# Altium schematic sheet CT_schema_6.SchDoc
size 368 x 336 mm
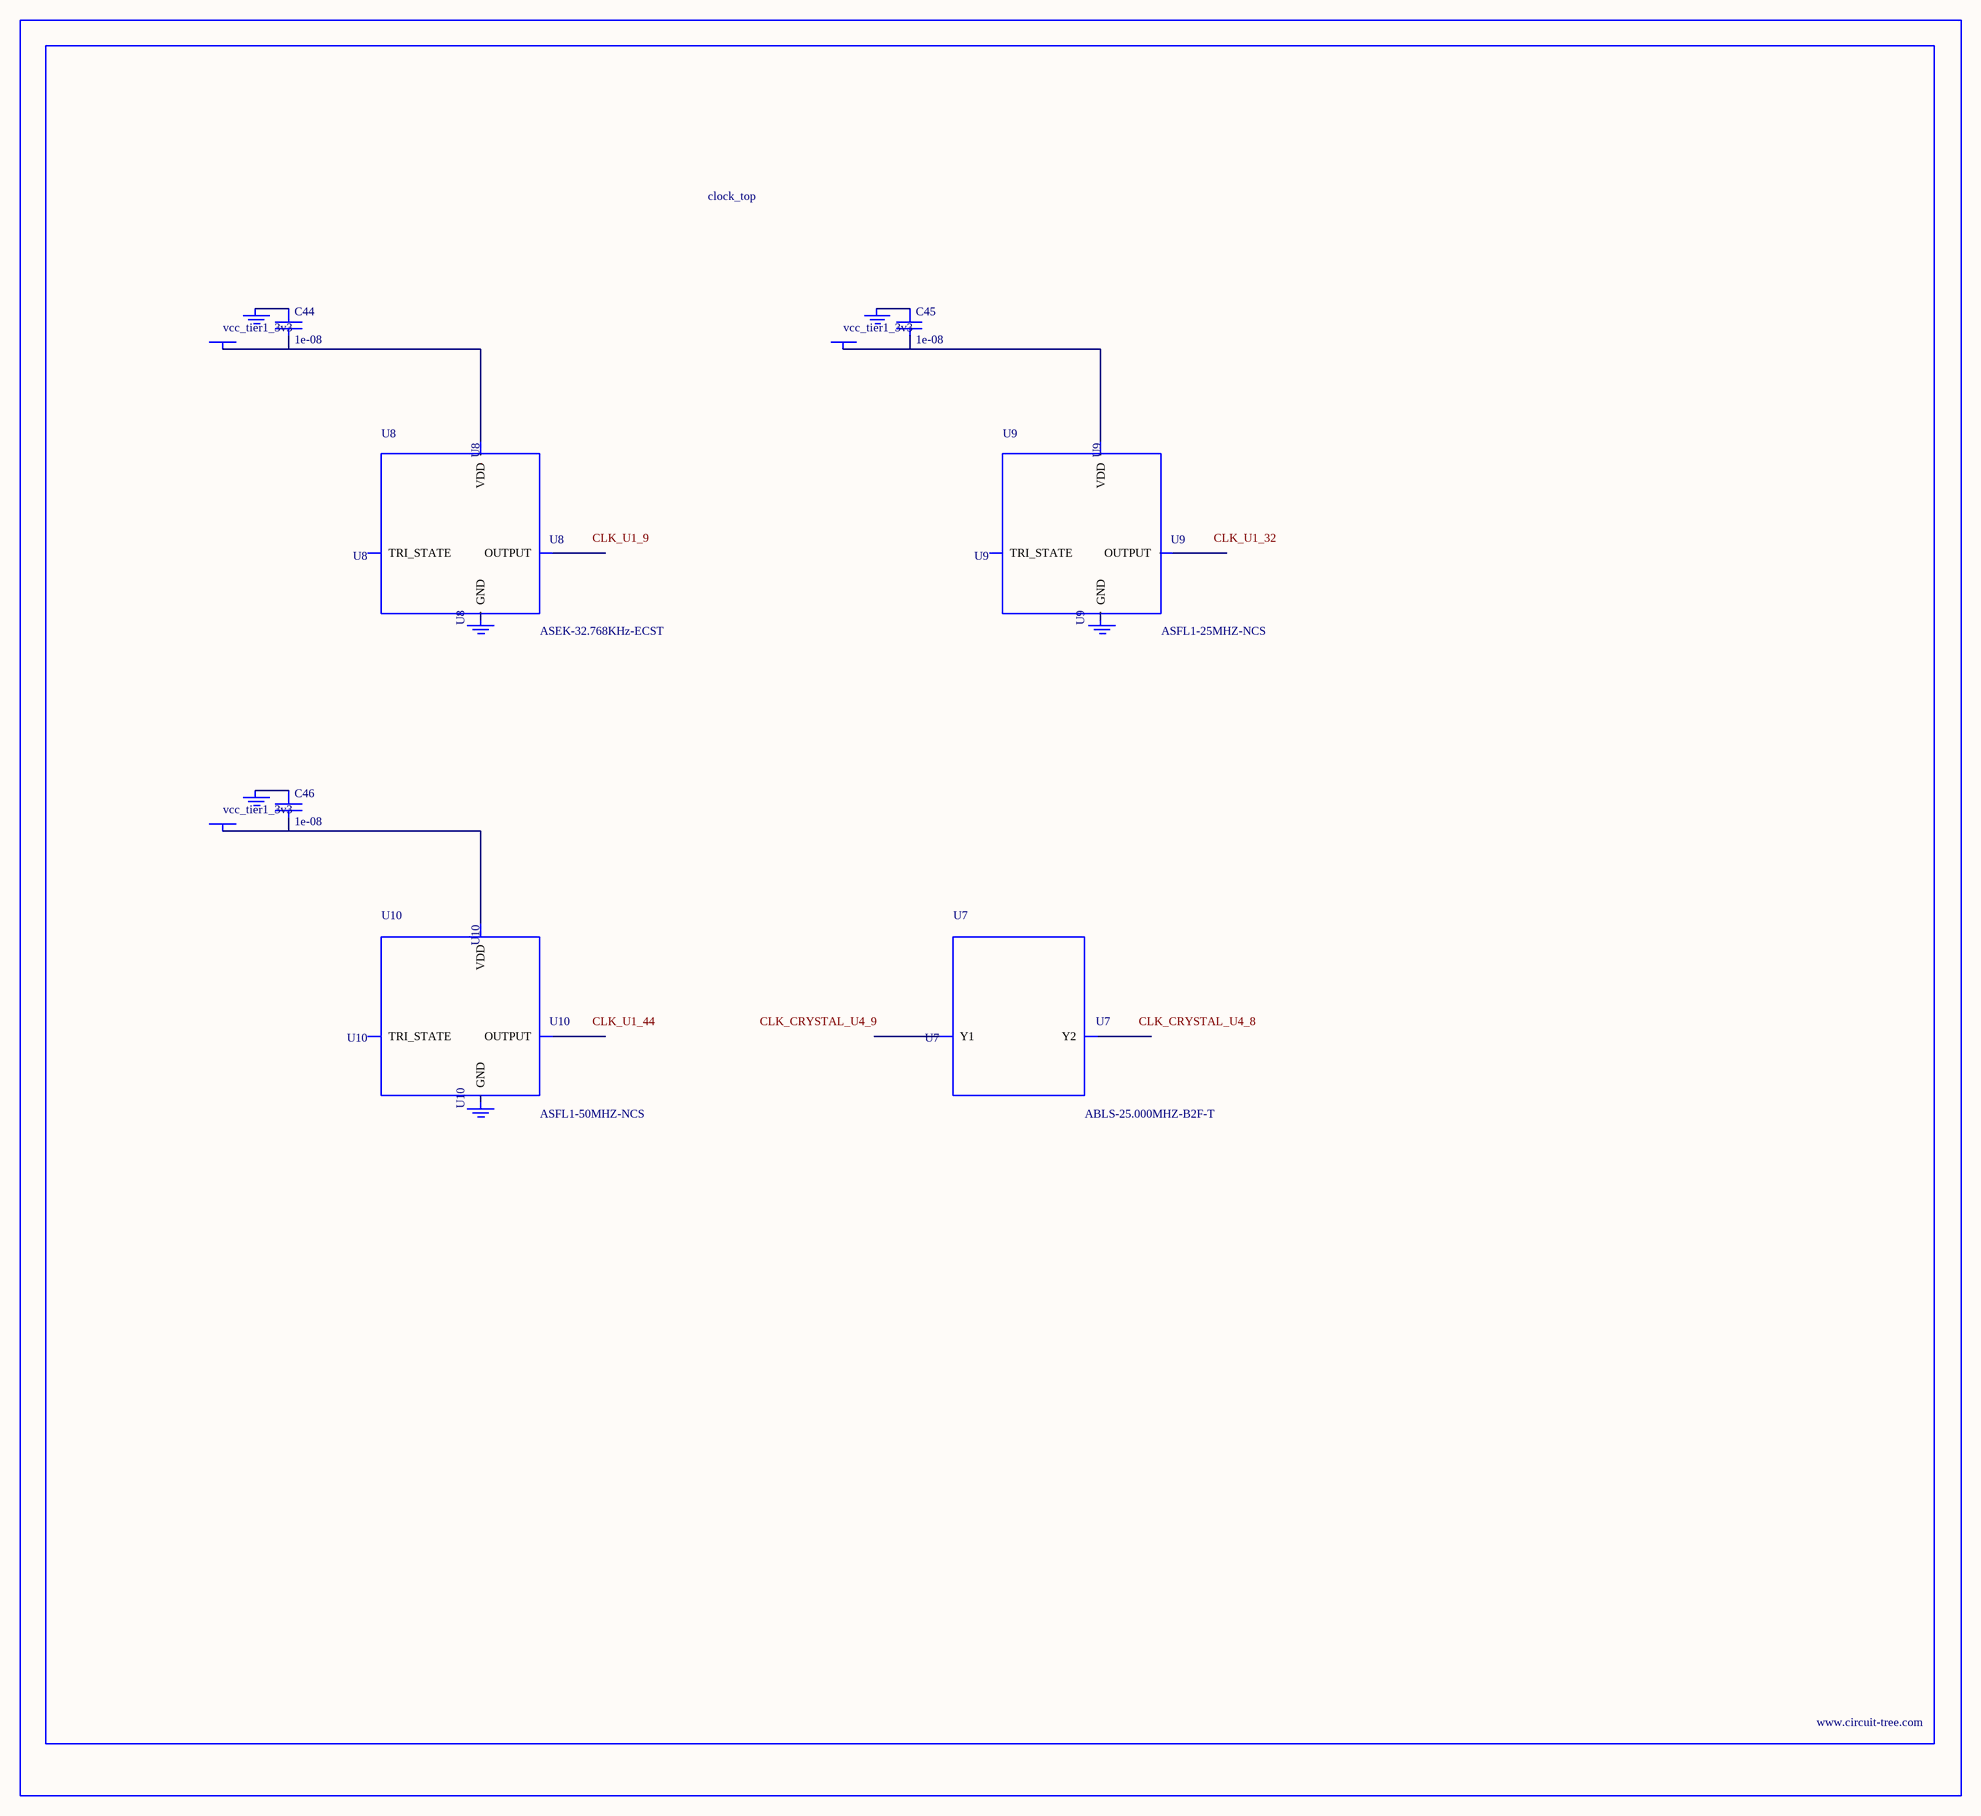
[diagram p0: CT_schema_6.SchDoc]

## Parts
BORDER5  (no value)
C44  1e-08  [C0402]
C45  1e-08  [C0402]
C46  1e-08  [C0402]
GND_INSTANCE_5_0  (no value)
GND_INSTANCE_5_1  (no value)
GND_INSTANCE_5_2  (no value)
GND_INSTANCE_5_3  (no value)
GND_INSTANCE_5_4  (no value)
GND_INSTANCE_5_5  (no value)
POWER_INSTANCE_5_0  vcc_tier1_3v3
POWER_INSTANCE_5_1  vcc_tier1_3v3
POWER_INSTANCE_5_2  vcc_tier1_3v3
U7  ABLS-25.000MHZ-B2F-T  [ABLS-25.000MHZ-B2F-T]
U8  ASEK-32.768KHz-ECST  [ASEK]
U9  ASFL1-25MHZ-NCS  [ASFL1]
U10  ASFL1-50MHZ-NCS  [ASFL1]

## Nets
NetC44_1: C44.1 GND_INSTANCE_5_0.0(GND)
NetC44_2: C44.2 POWER_INSTANCE_5_0.0(PWR) U8.4(VDD)
NetC45_1: C45.1 GND_INSTANCE_5_2.0(GND)
NetC45_2: C45.2 POWER_INSTANCE_5_1.0(PWR) U9.4(VDD)
NetC46_1: C46.1 GND_INSTANCE_5_4.0(GND)
NetC46_2: C46.2 POWER_INSTANCE_5_2.0(PWR) U10.4(VDD)

Not connected (* = marked no-connect by the designer): GND_INSTANCE_5_1 0(GND); GND_INSTANCE_5_3 0(GND); GND_INSTANCE_5_5 0(GND); U7 1(Y1) 2(Y2); U8 1(TRI_STATE) 2(GND) 3(OUTPUT); U9 1(TRI_STATE) 2(GND) 3(OUTPUT); U10 1(TRI_STATE) 2(GND) 3(OUTPUT)

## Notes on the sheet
- Labels drawn without touching a wire or pin: CLK_CRYSTAL_U4_8, CLK_CRYSTAL_U4_9, CLK_U1_9, CLK_U1_32, CLK_U1_44

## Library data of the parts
BORDER5 = BORDER_PAGE5
C44-C46 = C0402C103K3RAC
GND_INSTANCE_5_0-GND_INSTANCE_5_5 = GND
POWER_INSTANCE_5_0-POWER_INSTANCE_5_2 = PWR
